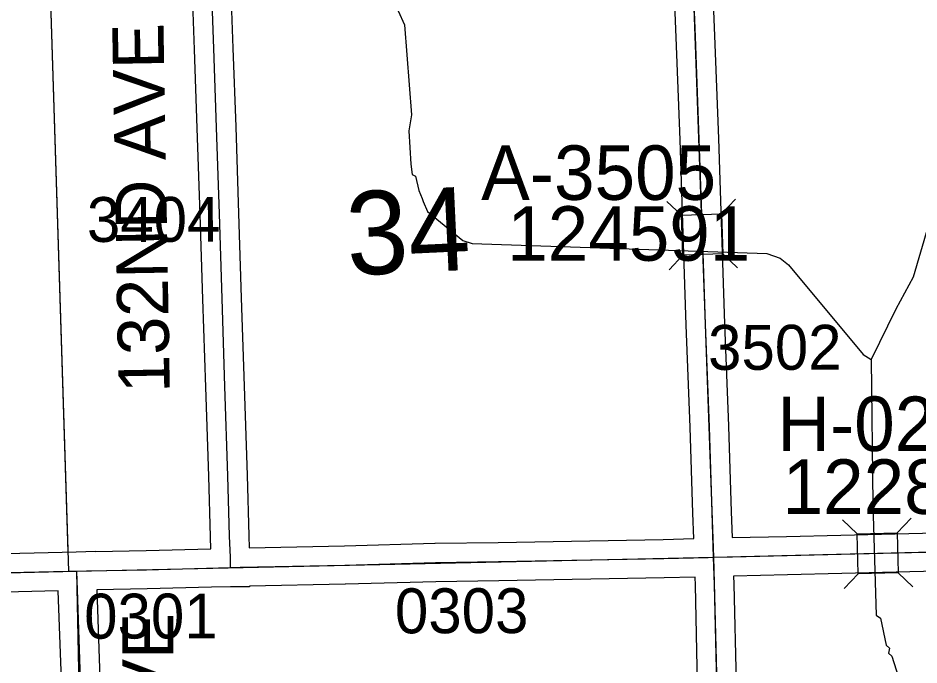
# Model space of a CAD drawing. Extents: x 128.7 to 185.5, y -21.4 to 12.6.
# Drawn here: x 136.899 to 138.305, y -1.752 to -0.743 of the extents above; entities that cross this region are included whole.
import ezdxf

# ---------------------------------------------------------------- set-up
doc = ezdxf.new("R2010")
doc.units = 0
for name, color, linetype in [('tdCoHydroRiver', 7, 'Continuous'), ('tdCoSecRdNmbr', 7, 'Continuous'), ('tdCoSecRdTxt', 7, 'Continuous'), ('tdCoSecRteBand', 7, 'Continuous'), ('tdCoSecRteCL', 7, 'Continuous'), ('tdCoSectLine', 7, 'Continuous'), ('tdCoSectLinePart', 7, 'Continuous'), ('tdCoSectNmbr', 7, 'Continuous'), ('tdCoStrucSec', 7, 'Continuous'), ('tdCoStrucSecCoName', 7, 'Continuous'), ('tdCoStrucSecFHWANum', 7, 'Continuous'), ('tdCoSurfAsphalt', 7, 'Continuous'), ('tdCoSurfGravel', 7, 'Continuous'), ('tdCoTwpBndryShd', 7, 'Continuous')]:
    doc.layers.add(name, color=color, linetype=linetype)

msp = doc.modelspace()

# ---------------------------------------------------------------- linework, layer by layer
at = {"layer": 'tdCoHydroRiver'}
for points in [[(137.4924, -0.7323), (137.5025, -0.7541), (137.5132, -0.8942), (137.5093, -0.9195), (137.5125, -0.9715), (137.5146, -0.9872), (137.5194, -0.9902), (137.5248, -1.0121), (137.5299, -1.0246), (137.5317, -1.0293), (137.5385, -1.0449), (137.5935, -1.0905), (137.6079, -1.0948), (138.0676, -1.1104), (138.0883, -1.1176), (138.1013, -1.1282), (138.2177, -1.2682), (138.2305, -1.2757), (138.2328, -1.5013), (138.2372, -1.64), (138.2383, -1.6747), (138.2447, -1.6792), (138.2539, -1.7215), (138.2588, -1.7261), (138.2575, -1.734), (138.2624, -1.7386), (138.2729, -1.7714)], [(138.3188, -1.0694), (138.2959, -1.1474), (138.2691, -1.1972), (138.2305, -1.2757)]]:
    msp.add_lwpolyline(points, dxfattribs=at)
at = {"layer": 'tdCoSecRteBand'}
for points in [[(137.2601, -1.5694), (137.4086, -1.5665), (137.5498, -1.5623), (137.5501, -1.5623), (137.5503, -1.5623), (137.6486, -1.561), (137.9061, -1.5563), (137.9536, -1.555), (137.9522, -1.5155), (137.9522, -1.5155), (137.9522, -1.5154), (137.948, -1.3816), (137.9419, -1.2224), (137.9419, -1.2223), (137.9419, -1.2223), (137.9372, -1.0795), (137.9322, -0.9333), (137.9261, -0.7736), (137.9204, -0.6304)], [(137.9804, -0.6281), (137.986, -0.7713), (137.986, -0.7713), (137.986, -0.7713), (137.9922, -0.9311), (137.9922, -0.9312), (137.9922, -0.9312), (137.9971, -1.0775), (137.9971, -1.0775), (137.9971, -1.0775), (138.0018, -1.2202), (138.008, -1.3794), (138.008, -1.3795), (138.008, -1.3796), (138.0122, -1.5135), (138.0136, -1.5532), (138.0136, -1.5536)], [(137.2301, -0.6591), (137.2348, -0.7902), (137.2392, -0.9132), (137.2392, -0.9133), (137.2392, -0.9133), (137.2436, -1.048), (137.2436, -1.048), (137.2436, -1.048), (137.2478, -1.1797), (137.2523, -1.3172), (137.257, -1.4561), (137.257, -1.4562), (137.257, -1.4563), (137.2594, -1.5506), (137.2601, -1.5694)], [(136.8363, -1.5795), (136.9904, -1.5757), (137.0203, -1.5748), (137.0203, -1.575), (137.0205, -1.575), (137.0205, -1.5751), (137.0995, -1.5736), (137.2002, -1.5709), (137.1995, -1.5527), (137.1995, -1.5525), (137.1995, -1.5523), (137.197, -1.458), (137.1923, -1.3192), (137.1923, -1.3192), (137.1923, -1.3192), (137.1879, -1.1816), (137.1879, -1.1816), (137.1879, -1.1816), (137.1837, -1.0499), (137.1792, -0.9153), (137.1748, -0.7923), (137.1748, -0.7923), (137.1748, -0.7923), (137.1701, -0.6611)], [(138.0136, -1.5536), (138.0984, -1.5517), (138.2678, -1.5475), (138.2678, -1.5475), (138.2678, -1.5475), (138.439, -1.5433)], [(138.9674, -1.8968), (138.9622, -1.7513), (138.9622, -1.7512), (138.9622, -1.7512), (138.9585, -1.6286), (138.9573, -1.5904), (138.957, -1.5904), (138.8844, -1.5922), (138.7165, -1.5968), (138.7164, -1.5969), (138.7164, -1.5969), (138.5341, -1.601), (138.4404, -1.6033), (138.2693, -1.6075), (138.0999, -1.6116), (138.0999, -1.6116), (138.0998, -1.6116), (138.0157, -1.6136), (138.0161, -1.6256), (138.0161, -1.6258), (138.0161, -1.626), (138.0196, -1.7798)], [(137.9596, -1.7813), (137.9562, -1.6276), (137.9557, -1.615), (137.9076, -1.6163), (137.9075, -1.6163), (137.9073, -1.6163), (137.6496, -1.621), (137.6496, -1.621), (137.6495, -1.621), (137.5513, -1.6223), (137.4103, -1.6264), (137.4101, -1.6264), (137.41, -1.6264), (137.2607, -1.6294), (137.2607, -1.6301), (137.2311, -1.6301), (137.2015, -1.6309), (137.101, -1.6336), (137.1008, -1.6336), (137.1007, -1.6336), (137.0222, -1.635), (137.0271, -1.7729)], [(136.9671, -1.7752), (136.9622, -1.6364), (136.962, -1.6364), (136.8378, -1.6395)]]:
    msp.add_lwpolyline(points, dxfattribs=at)
at = {"layer": 'tdCoSecRteCL'}
for points in [[(137.9846, -1.5842), (137.9822, -1.5145), (137.978, -1.3806), (137.9718, -1.2213), (137.9672, -1.0785), (137.9622, -0.9323), (137.9561, -0.7725), (137.9504, -0.6292), (137.9494, -0.5949), (137.949, -0.582)], [(137.2307, -1.6001), (137.2307, -1.5841), (137.2294, -1.5515), (137.227, -1.4571), (137.2223, -1.3182), (137.2179, -1.1806), (137.2137, -1.0489), (137.2092, -0.9143), (137.2048, -0.7912), (137.2001, -0.66), (137.1984, -0.5982)], [(137.9846, -1.5842), (138.0141, -1.5836), (138.0991, -1.5817), (138.2686, -1.5775), (138.4397, -1.5733), (138.5334, -1.5711), (138.7157, -1.5669), (138.8836, -1.5622), (138.9863, -1.5598)], [(137.2307, -1.6001), (137.2459, -1.5997), (137.4094, -1.5965), (137.5507, -1.5923), (137.6491, -1.591), (137.9068, -1.5863), (137.9761, -1.5844), (137.9846, -1.5842)], [(138.0445, -3.5917), (138.0438, -3.5214), (138.0421, -3.4444), (138.0372, -3.3194), (138.033, -3.1882), (138.0286, -3.0548), (138.0231, -2.9184), (138.0182, -2.7769), (138.012, -2.6309), (138.0086, -2.4982), (138.0054, -2.3522), (138.0009, -2.2065), (137.997, -2.0588), (137.9933, -1.9147), (137.9896, -1.7806), (137.9861, -1.6267), (137.9846, -1.5842)], [(136.9912, -1.6057), (137.0062, -1.6053), (137.1001, -1.6036), (137.2307, -1.6001)], [(135.8268, -1.6317), (135.9401, -1.6293), (136.0614, -1.6268), (136.2104, -1.6231), (136.3835, -1.6186), (136.5463, -1.6157), (136.6883, -1.6127), (136.837, -1.6095), (136.9912, -1.6057)], [(136.9971, -1.7741), (136.9922, -1.6352), (136.9912, -1.6057)]]:
    msp.add_lwpolyline(points, dxfattribs=at)
at = {"layer": 'tdCoSectLine'}
for points in [[(137.9486, -0.582), (137.9843, -1.5842)], [(136.9465, -0.6032), (136.9783, -1.606)], [(137.9843, -1.5842), (138.9859, -1.5598)], [(136.9908, -1.6057), (137.9843, -1.5842)], [(137.9843, -1.5842), (138.0106, -2.5918)], [(135.9787, -1.6285), (136.9783, -1.606)], [(136.9783, -1.606), (136.9908, -1.6057)], [(136.9908, -1.6057), (137.0109, -2.6063)]]:
    msp.add_lwpolyline(points, dxfattribs=at)
at = {"layer": 'tdCoSectLinePart'}
msp.add_lwpolyline([(136.9465, -0.6032), (136.9774, -1.5759)], dxfattribs=at)
at = {"layer": 'tdCoStrucSec'}
for p, q in [((137.9971, -1.0488), (138.0185, -1.0259)), ((137.9345, -1.0508), (137.9117, -1.0294)), ((137.9366, -1.1134), (137.9152, -1.1362)), ((137.9992, -1.1113), (138.022, -1.1327)), ((138.2086, -1.5476), (138.1859, -1.5261)), ((138.2712, -1.5461), (138.2927, -1.5234)), ((138.2101, -1.6102), (138.1885, -1.6329)), ((138.2727, -1.6087), (138.2954, -1.6302))]:
    msp.add_line(p, q, dxfattribs=at)
for points in [[(137.9366, -1.1134), (137.9345, -1.0508), (137.9971, -1.0488), (137.9992, -1.1113)], [(138.2086, -1.5476), (138.2712, -1.5461), (138.2727, -1.6087), (138.2101, -1.6102)]]:
    msp.add_lwpolyline(points, close=True, dxfattribs=at)
at = {"layer": 'tdCoSurfAsphalt'}
msp.add_lwpolyline([(137.9896, -1.7806), (137.9861, -1.6267), (137.9846, -1.5842), (137.9822, -1.5145), (137.978, -1.3806), (137.9718, -1.2213), (137.9672, -1.0785), (137.9622, -0.9323), (137.9561, -0.7725), (137.9504, -0.6292), (137.9494, -0.5949), (137.949, -0.582), (138.0194, -0.5806), (138.0686, -0.5788), (138.1326, -0.5766), (138.1686, -0.5754), (138.1996, -0.5746), (138.2841, -0.5724)], dxfattribs=at)
at = {"layer": 'tdCoSurfGravel'}
for points in [[(137.2307, -1.6001), (137.2307, -1.5841), (137.2294, -1.5515), (137.227, -1.4571), (137.2223, -1.3182), (137.2179, -1.1806), (137.2137, -1.0489), (137.2092, -0.9143), (137.2048, -0.7912), (137.2001, -0.66), (137.1984, -0.5982)], [(136.9912, -1.6057), (137.0062, -1.6053), (137.1001, -1.6036), (137.2307, -1.6001), (137.2459, -1.5997), (137.4094, -1.5965), (137.5507, -1.5923), (137.6491, -1.591), (137.9068, -1.5863), (137.9761, -1.5844), (137.9846, -1.5842), (138.0141, -1.5836), (138.0991, -1.5817), (138.2686, -1.5775), (138.4397, -1.5733)], [(135.8268, -1.6317), (135.8268, -1.6317), (135.9401, -1.6293), (136.0614, -1.6268), (136.2104, -1.6231), (136.3835, -1.6186), (136.5463, -1.6157), (136.6883, -1.6127), (136.837, -1.6095), (136.9912, -1.6057)], [(136.9922, -2.3408), (136.9922, -2.3398), (136.9875, -2.2498), (136.9793, -2.1075), (136.9729, -1.9987), (136.9724, -1.9869), (136.9734, -1.9743), (136.9754, -1.9558), (136.9818, -1.9102), (136.9848, -1.888), (136.988, -1.8717), (136.9924, -1.8547), (136.9981, -1.8372), (136.9991, -1.8177), (136.9971, -1.7741), (136.9922, -1.6352), (136.9912, -1.6057)]]:
    msp.add_lwpolyline(points, dxfattribs=at)
at = {"layer": 'tdCoTwpBndryShd'}
msp.add_lwpolyline([(133.9673, -1.6731), (134.9785, -1.6501), (135.9787, -1.6285), (136.9783, -1.606), (136.9908, -1.6057), (137.9843, -1.5842), (138.9859, -1.5598), (139.9867, -1.5369), (141.001, -1.5077), (142.0055, -1.4764), (143.0036, -1.4478), (143.9967, -1.4154), (144.999, -1.3795), (146.001, -1.3445), (147.0006, -1.3151), (147.9961, -1.2801), (149.0001, -1.2471), (150.0007, -1.2153), (150.9999, -1.1762), (152.001, -1.1385), (152.9972, -1.0884), (154.0014, -1.05)], dxfattribs=at)

# ---------------------------------------------------------------- texts
at = {"layer": 'tdCoSecRdNmbr'}
for s, rotation, p in [('3404', 0.1046, (137.007, -1.0926)), ('3502', 0.1053, (137.976, -1.2921)), ('0301', 0.1046, (137.0027, -1.7111)), ('0303', 0.1049, (137.4875, -1.7028))]:
    msp.add_text(s, height=0.07, rotation=rotation, dxfattribs=at).set_placement(p)
at = {"layer": 'tdCoSecRdTxt'}
for s, rotation, p in [('132ND AVE', 91, (137.1364, -1.3276)), ('130 AVE', 90, (137.142, -2.0936))]:
    msp.add_text(s, height=0.08, rotation=rotation, dxfattribs=at).set_placement(p)
at = {"layer": 'tdCoSectNmbr'}
msp.add_text('34', height=0.13, rotation=2.6572, dxfattribs=at).set_placement((137.4142, -1.1449))
at = {"layer": 'tdCoStrucSecCoName'}
for s, p in [('A-3505', (137.622, -1.027)), ('H-0220', (138.084, -1.4186))]:
    msp.add_text(s, height=0.085, dxfattribs=at).set_placement(p)
at = {"layer": 'tdCoStrucSecFHWANum'}
for s, p in [('124591', (137.6626, -1.1219)), ('122833', (138.0922, -1.5166))]:
    msp.add_text(s, height=0.085, dxfattribs=at).set_placement(p)

doc.saveas('drawing.dxf')
